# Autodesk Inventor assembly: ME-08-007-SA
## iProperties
Shininess: 20.0
Length Units: 11269
Angle Units: 11279
Time Units: 11290
Mass Units: 11283
Length Display Precision: 3
Angle Display Precision: 2
Created: 2001-04
Part Number: ME-08-007-SA
Document SubType Name: Baugruppe
Designer: dl
Density: 0.0
Volumn: 0.0
Area: 0.0
PropertySet Name: Model Information
Control State: 0
Master: False
Checked Out: False
Author: dl
